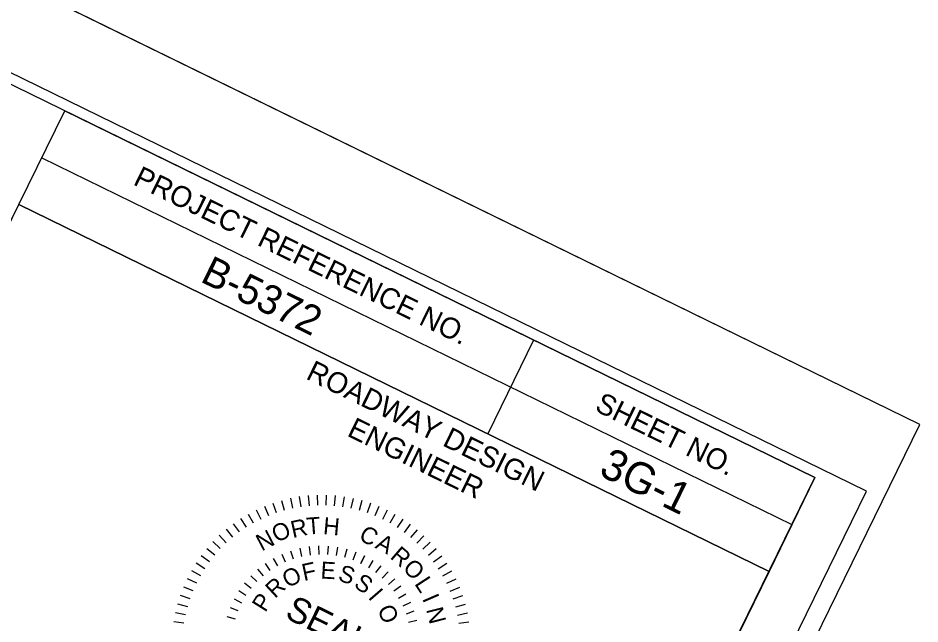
# Model space of a CAD drawing. Extents: x 1518400 to 1523182, y 633375 to 639930.
# Drawn here: x 1522685.9 to 1523118.1, y 635247.1 to 635537.5 of the extents above; entities that cross this region are included whole.
import ezdxf

# ---------------------------------------------------------------- set-up
doc = ezdxf.new("R2010")
doc.units = 0
for name, color, linetype in [('Default', 7, 'Continuous'), ('Sheet Cutting Line CELL', 7, 'Continuous'), ('Sheet Data Field CELL', 7, 'Continuous'), ('Sheet Plan CELL', 7, 'Continuous'), ('Sheet Plot Border Inside CELL', 7, 'Continuous'), ('Sheet Plot Border Outside CELL', 7, 'Continuous')]:
    doc.layers.add(name, color=color, linetype=linetype)

msp = doc.modelspace()

# ---------------------------------------------------------------- linework, layer by layer
at = {"layer": 'Default'}
for p, q in [((1522808.1, 635305.1), (1522809.68, 635300.49)), ((1522812.23, 635306.37), (1522813.53, 635301.67)), ((1522816.43, 635307.4), (1522817.44, 635302.63)), ((1522820.68, 635308.16), (1522821.4, 635303.34)), ((1522824.97, 635308.68), (1522825.4, 635303.82)), ((1522829.29, 635308.93), (1522829.42, 635304.05)), ((1522833.61, 635308.91), (1522833.44, 635304.04)), ((1522837.92, 635308.64), (1522837.47, 635303.78)), ((1522842.21, 635308.11), (1522841.46, 635303.29)), ((1522846.46, 635307.32), (1522845.42, 635302.56)), ((1522850.65, 635306.27), (1522849.33, 635301.58)), ((1522854.77, 635304.97), (1522853.17, 635300.37)), ((1522800.11, 635301.81), (1522802.24, 635297.43)), ((1522804.06, 635303.58), (1522805.91, 635299.07)), ((1522858.8, 635303.43), (1522856.92, 635298.93)), ((1522862.74, 635301.65), (1522860.6, 635297.27)), ((1522792.58, 635297.6), (1522795.21, 635293.49)), ((1522796.28, 635299.82), (1522798.66, 635295.57)), ((1522866.56, 635299.63), (1522864.16, 635295.39)), ((1522870.25, 635297.38), (1522867.6, 635293.3)), ((1522785.61, 635292.49), (1522788.72, 635288.74)), ((1522789.01, 635295.15), (1522791.9, 635291.21)), ((1522873.81, 635294.92), (1522870.91, 635291)), ((1522877.2, 635292.25), (1522874.07, 635288.51)), ((1522782.36, 635289.64), (1522785.7, 635286.07)), ((1522880.43, 635289.37), (1522877.08, 635285.82)), ((1522776.42, 635283.36), (1522780.17, 635280.23)), ((1522779.3, 635286.59), (1522782.85, 635283.24)), ((1522820.93, 635283.42), (1522821.82, 635279.45)), ((1522825.41, 635284.2), (1522825.91, 635280.16)), ((1522829.96, 635284.54), (1522830.07, 635280.49)), ((1522834.51, 635284.45), (1522834.23, 635280.4)), ((1522839.04, 635283.92), (1522838.36, 635279.91)), ((1522883.47, 635286.31), (1522879.91, 635282.98)), ((1522773.75, 635279.97), (1522777.67, 635277.07)), ((1522812.28, 635280.58), (1522813.92, 635276.86)), ((1522816.54, 635282.2), (1522817.81, 635278.34)), ((1522843.49, 635282.95), (1522842.43, 635279.02)), ((1522847.82, 635281.55), (1522846.4, 635277.75)), ((1522852.01, 635279.75), (1522850.22, 635276.1)), ((1522850.22, 635276.1), (1522852.01, 635279.75)), ((1522886.32, 635283.06), (1522882.58, 635279.95)), ((1522888.99, 635279.66), (1522885.05, 635276.78)), ((1522771.29, 635276.42), (1522775.38, 635273.76)), ((1522804.35, 635276.13), (1522806.66, 635272.79)), ((1522808.2, 635278.55), (1522810.19, 635275)), ((1522856, 635277.55), (1522853.87, 635274.09)), ((1522859.75, 635274.98), (1522857.3, 635271.74)), ((1522891.43, 635276.09), (1522887.33, 635273.46)), ((1522769.05, 635272.73), (1522773.29, 635270.32)), ((1522797.41, 635270.23), (1522800.33, 635267.41)), ((1522800.73, 635273.35), (1522803.36, 635270.25)), ((1522863.25, 635272.05), (1522860.49, 635269.06)), ((1522893.66, 635272.39), (1522889.4, 635270.01)), ((1522767.03, 635268.9), (1522771.41, 635266.76)), ((1522794.4, 635266.82), (1522797.58, 635264.28)), ((1522866.44, 635268.8), (1522863.41, 635266.09)), ((1522895.65, 635268.56), (1522891.27, 635266.44)), ((1522765.24, 635264.97), (1522769.74, 635263.09)), ((1522791.73, 635263.12), (1522795.14, 635260.91)), ((1522869.3, 635265.26), (1522866.03, 635262.86)), ((1522897.42, 635264.61), (1522892.91, 635262.76)), ((1522763.7, 635260.93), (1522768.3, 635259.33)), ((1522789.44, 635259.19), (1522793.04, 635257.31)), ((1522871.82, 635261.46), (1522868.32, 635259.38)), ((1522873.95, 635257.43), (1522870.26, 635255.7)), ((1522898.93, 635260.57), (1522894.32, 635258.99)), ((1522762.4, 635256.81), (1522767.09, 635255.49)), ((1522787.53, 635255.05), (1522791.3, 635253.53)), ((1522875.67, 635253.21), (1522871.84, 635251.85)), ((1522900.21, 635256.44), (1522895.51, 635255.15)), ((1522761.36, 635252.62), (1522766.12, 635251.58)), ((1522786.04, 635250.75), (1522789.93, 635249.6)), ((1522876.99, 635248.85), (1522873.05, 635247.87)), ((1522901.23, 635252.24), (1522896.47, 635251.23)), ((1522760.56, 635248.37), (1522765.39, 635247.62)), ((1522902, 635247.99), (1522897.18, 635247.27))]:
    msp.add_line(p, q, dxfattribs=at)
at = {"layer": 'Sheet Cutting Line CELL'}
msp.add_line((1523118.12, 635342.8), (1520093.48, 636822.08), dxfattribs=at)
at = {"layer": 'Sheet Plan CELL'}
for p, q in [((1522697.36, 635470.55), (1523056.78, 635294.76)), ((1522686.38, 635448.09), (1523045.79, 635272.3)), ((1522686.38, 635448.09), (1523045.79, 635272.3)), ((1522933.01, 635383.12), (1522911.04, 635338.21))]:
    msp.add_line(p, q, dxfattribs=at)
for points in [[(1523067.8, 635317.31), (1520372.85, 636635.35), (1519450.22, 634748.89), (1522145.17, 633430.84)], [(1522708.39, 635493.09), (1523067.8, 635317.31), (1523045.79, 635272.3), (1522686.38, 635448.09)], [(1522686.38, 635448.09), (1523045.79, 635272.3), (1522946.94, 635070.18), (1522587.52, 635245.97)], [(1522686.38, 635448.09), (1523045.79, 635272.3), (1522946.95, 635070.21), (1522587.53, 635245.99)]]:
    msp.add_lwpolyline(points, close=True, dxfattribs=at)
at = {"layer": 'Sheet Plot Border Inside CELL'}
msp.add_lwpolyline([(1519172.24, 634879.28), (1522165.43, 633415.37), (1523092.46, 635310.82), (1520099.27, 636774.73)], close=True, dxfattribs=at)
at = {"layer": 'Sheet Plot Border Outside CELL'}
msp.add_lwpolyline([(1519131.31, 634854.77), (1522155.94, 633375.48), (1523118.12, 635342.8), (1520093.48, 636822.08)], close=True, dxfattribs=at)

# ---------------------------------------------------------------- texts
at = {"layer": 'Default'}
for s, height, rotation, p in [('R', 8.12, 12.5453, (1522817.58, 635288.24)), ('T', 8.12, 4.3843, (1522824.48, 635289.92)), ('H', 8.12, 354.9524, (1522831.91, 635290.22)), ('N', 8.12, 27.5614, (1522802.68, 635281.82)), ('O', 8.12, 25.602, (1522809.89, 635285.92)), ('C', 8.12, 331.2417, (1522848.71, 635287.79)), ('A', 8.12, 331.2417, (1522856.61, 635283.74)), ('R', 8.12, 319.2324, (1522863.81, 635278.88)), ('F', 8.12, 12.1253, (1522822.9, 635267.68)), ('E', 8.12, 356.8291, (1522830.76, 635268.94)), ('S', 8.12, 341.5328, (1522838.83, 635268.09)), ('O', 8.12, 316.1756, (1522869.84, 635273.32)), ('O', 8.12, 27.4216, (1522815.17, 635264.17)), ('S', 8.12, 326.2366, (1522846.41, 635265.13)), ('R', 8.12, 42.7178, (1522809.07, 635259.04)), ('L', 8.12, 303.0393, (1522875.67, 635266.43)), ('P', 8.12, 58.0141, (1522804.43, 635252.35)), ('I', 8.12, 310.9403, (1522853.39, 635259.75)), ('I', 8.12, 293.4638, (1522879.47, 635259.32)), ('SEAL', 12.189, 333.8847, (1522813.26, 635250.31)), ('O', 8.12, 295.6441, (1522857.88, 635254.03)), ('N', 8.12, 284.1693, (1522881.44, 635254.09))]:
    msp.add_text(s, height=height, rotation=rotation, dxfattribs=at).set_placement(p)
at = {"layer": 'Sheet Data Field CELL'}
for s, height, p in [('B-5372', 14, (1522772.76, 635411.44)), ('3G-1', 15, (1522963.63, 635318.72))]:
    msp.add_text(s, height=height, rotation=333.9377, dxfattribs=at).set_placement(p)
at = {"layer": 'Sheet Plan CELL'}
for s, height, p in [('PROJECT REFERENCE NO.', 10.0002, (1522740.63, 635457.96)), ('ROADWAY DESIGN', 10.0002, (1522823.4, 635364.82)), ('SHEET NO.', 10, (1522961.79, 635349.56)), ('ENGINEER', 10, (1522843.1, 635337.49))]:
    msp.add_text(s, height=height, rotation=333.9377, dxfattribs=at).set_placement(p)

doc.saveas('drawing.dxf')
